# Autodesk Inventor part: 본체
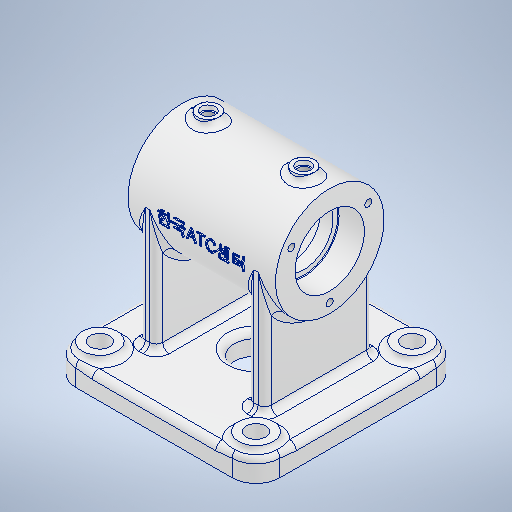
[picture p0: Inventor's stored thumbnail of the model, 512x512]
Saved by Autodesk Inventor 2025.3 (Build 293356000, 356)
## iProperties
Created: 2025-10
Part Number: 본체
Material: 알루미늄 6061
Document SubType Name: Modeling
Designer: USER
Density: 2.7 g/cm^3
Appearance: 알루미늄 - 평지
Mass: 504.67 g
Surface Area: 500.812 cm^2
Volume: 186.915 cm^3
Author: USER
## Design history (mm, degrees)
sketch "스케치1"
  geometry: L1 (-34, 0)-(34, 0); L2 (-34, 0)-(-34, 16); L3 (-34, 16)-(-22.3, 16); L4 (-22, 15.7)-(-22, 13.5); L5 (-22, 13.5)-(-16.258, 13.5); L6 (-16.258, 13.5)-(-5, 20); L7 (-5, 20)-(5, 20); L8 (5, 20)-(16.258, 13.5); L9 (16.258, 13.5)-(22, 13.5); L10 (22, 13.5)-(22, 15.7); L11 (22.3, 16)-(34, 16); L12 (34, 16)-(34, 0); L13 (-34, 25)-(34, 25); L14 (-34, 25)-(-34, 16); L15 (34, 25)-(34, 16); A1 r 0.3 centre (-22.3, 15.7) between (-22, 15.7) and (-22.3, 16); A2 r 0.3 centre (22.3, 15.7) between (22.3, 16) and (22, 15.7); 3 further points
  constraints: 30 end point, 6 perpendicular, 4 point on circle, 4 tangent, 3 vertical, 3 vertical alignment, 2 centre point, 2 coincident, 2 midpoint, 2 point on line, 1 equal radius, 1 horizontal, 1 parallel
  dimensions: "d0" = 12 distance between parallel lines of L4 L2; "d1" = 32 diameter of L3 L1; "d2" = 27 diameter of L5 L1; "d3" = 40 diameter of L7 L1; "d4" = 30 deg angle of L1 L6; "d5" = 30 deg angle of L1 L8; "d6" = 10 distance of L7.end L6.end; "d8" = 32 diameter of L11 L1; "d9" = 12 distance between parallel lines of L10 L12; "d10" = 68 distance between parallel lines of L12 L2; "d11" = 50 diameter of L13 L1; "d12" = 0.3 radius of A1 (derived)
revolve "회전1" sketch "스케치1" stored, may be unused: angle "d13" = 90 deg
node "작업 평면1"
sketch "스케치2"
  geometry: L1 (36, -47)-(-36, -47); L2 (-47, -36)-(-47, 36); L3 (-36, 47)-(36, 47); L4 (47, 36)-(47, -36); L5 (47, -47)-(-47, 47); L6 (-47, -47)-(47, 47); A1 r 11 centre (-36, 36) between (-36, 47) and (-47, 36); A2 r 11 centre (36, 36) between (47, 36) and (36, 47); A3 r 11 centre (36, -36) between (36, -47) and (47, -36); A4 r 11 centre (-36, -36) between (-47, -36) and (-36, -47); 1 further point
  constraints: 12 end point, 8 point on circle, 8 point on line, 8 tangent, 4 centre point, 2 equal radius, 2 midpoint, 2 parallel, 1 horizontal, 1 perpendicular
  dimensions: "d15" = 94 distance between parallel lines of L1 L3; "d16" = 94 distance between parallel lines of L2 L4; "d17" = 11 radius of A1; "d18" = 11 radius of A2
extrude "돌출1" join sketch "스케치2" distance "d19" = 10; taper "d20" = 0 deg
sketch "스케치4"
  geometry: L1 (-36, -47)-(36, -47) reference; L2 (47, -36)-(47, 36) reference; L3 (-36, -47)-(36, -47) reference; L4 (-47, 36)-(-47, -36) reference; L5 (36, 47)-(-36, 47) reference; L6 (47, -36)-(47, 36) reference; C1 r 8 at (36, -36); C2 r 8 at (-36, -36); C3 r 8 at (-36, 36); C4 r 8 at (36, 36); A1 r 11 centre (36, -36) between (36, -47) and (47, -36) reference; A2 r 11 centre (-36, -36) between (-47, -36) and (-36, -47) reference; A3 r 11 centre (-36, 36) between (-36, 47) and (-47, 36) reference; A4 r 11 centre (36, 36) between (47, 36) and (36, 47) reference; A5 r 11 centre (36, -36) between (36, -47) and (47, -36) reference; 1 further point
  constraints: 4 centre point, 4 coincident
  dimensions: "d29" = 16 diameter of C1; "d30" = 16 diameter of C2; "d31" = 16 diameter of C3; "d32" = 16 diameter of C4
extrude "돌출3" join sketch "스케치4" distance "d33" = 3; taper "d34" = 0 deg
sketch "스케치5"
  geometry: C1 r 8 at (-72, 0) reference; C2 r 8 at (0, 0) reference; C3 r 8 at (0, 72) reference; C4 r 8 at (-72, 72) reference; C5 r 4.5 at (-72, 0); C6 r 4.5 at (0, 0); C7 r 4.5 at (0, 72); C8 r 4.5 at (-72, 72); 1 further point
  constraints: 4 centre point, 4 coincident
  dimensions: "d35" = 9 diameter of C5; "d36" = 9 diameter of C6; "d37" = 9 diameter of C7; "d38" = 9 diameter of C8
extrude "돌출4" cut sketch "스케치5" extent not by distance; stored distance "d39" = 0; taper "d40" = 0 deg
node "작업 평면2"
sketch "스케치6"
  geometry: L1 (34, 25)-(34, -25) reference; L2 (-34, 25)-(-34, -25) reference; C1 r 5 at (22, 0); C2 r 5 at (-22, 0); 1 further point
  constraints: 2 centre point, 2 horizontal alignment
  dimensions: "d41" = 12 distance from line of C1.centre L1; "d42" = 12 distance from line of C2.centre L2; "d43" = 10 diameter of C1; "d44" = 10 diameter of C2
extrude "돌출5" join sketch "스케치6" stored distance "d45" = 10; taper "d46" = 0 deg
extrude "돌출6" join sketch "스케치6" distance "d47" = 3; taper "d48" = 0 deg
sketch "스케치7"
  geometry: C1 r 5 at (0, 0) reference; C2 r 5 at (44, 0) reference; C3 r 3.3 at (0, 0); C4 r 3.3 at (44, 0); 1 further point
  constraints: 2 centre point, 2 coincident
  dimensions: "d49" = 6.6 diameter of C3; "d50" = 6.6 diameter of C4
extrude "돌출7" cut sketch "스케치7" distance "d51" = 2; taper "d52" = 0 deg
sketch "스케치8"
  geometry: C1 r 3.3 at (0, 0) reference; C2 r 3.3 at (44, 0) reference; 3 further points
  constraints: 2 coincident
hole "구멍1" sketch "스케치8" at (0, 0), (44, 0) diameter "d53" = 5.1881; stored, may be unused: countersink angle "d57" = 90 deg, drill point angle "d59" = 0 deg; dims "d54" = 12, "d55" = 4, "d56" = 2, "d58" = 16
node "작업 평면3"
sketch "스케치9"
  geometry: C1 r 6 at (0, 0); 1 further point
  constraints: 1 centre point, 1 coincident
  dimensions: "d60" = 12 diameter of C1
extrude "돌출8" join sketch "스케치9" stored distance "d61" = 10; taper "d62" = 0 deg
extrude "돌출9" join sketch "스케치9" distance "d63" = 3; taper "d64" = 0 deg
sketch "스케치10"
  geometry: 1 further point
hole "구멍2" sketch "스케치10" at (0, 0) diameter "d65" = 5.1881; stored, may be unused: countersink angle "d69" = 90 deg, drill point angle "d71" = 0 deg; dims "d66" = 12, "d67" = 4, "d68" = 2, "d70" = 16
sketch "스케치11"
  geometry: C1 r 25 at (0, 0) reference; C2 r 0.5 at (0, -20.5); C3 r 0.5 at (17.754, 10.25); C4 r 0.5 at (-17.754, 10.25); 2 further points
  constraints: 3 centre point, 2 vertical alignment, 1 coincident, 9 other
  dimensions: "d72" = 4.5 dimension on C1; "d73" = 1 diameter of C2; "d76" = 360 deg dimension on point (0, 0) C2.centre (derived)
hole "구멍3" sketch "스케치11" at (-17.754, 10.25), (0, -20.5), (17.754, 10.25) diameter "d78" = 3.242; stored, may be unused: countersink angle "d82" = 90 deg, drill point angle "d84" = 118 deg; dims "d79" = 8, "d80" = 4, "d81" = 2, "d83" = 10
sketch "스케치12"
  geometry: C1 r 10 at (0, 0); 1 further point
  constraints: 1 centre point, 1 coincident
  dimensions: "d85" = 20 diameter of C1
extrude "돌출10" cut sketch "스케치12" extent not by distance; stored distance "d86" = 0; taper "d87" = 0 deg
sketch "스케치13"
  geometry: L1 (26, -25)-(24, -25); L2 (21, -22)-(21, 22); L3 (24, 25)-(26, 25); L4 (29, 22)-(29, -22); L5 (-24, -25)-(-26, -25); L6 (-29, -22)-(-29, 22); L7 (-26, 25)-(-24, 25); L8 (-21, 22)-(-21, -22); A1 r 3 centre (26, -22) between (26, -25) and (29, -22); A2 r 3 centre (24, -22) between (21, -22) and (24, -25); A3 r 3 centre (24, 22) between (24, 25) and (21, 22); A4 r 3 centre (26, 22) between (29, 22) and (26, 25); A5 r 3 centre (-24, -22) between (-24, -25) and (-21, -22); A6 r 3 centre (-26, -22) between (-29, -22) and (-26, -25); A7 r 3 centre (-26, 22) between (-26, 25) and (-29, 22); A8 r 3 centre (-24, 22) between (-21, 22) and (-24, 25); 4 further points
  constraints: 16 end point, 16 point on circle, 16 tangent, 8 centre point, 6 equal radius, 4 parallel, 2 horizontal, 2 horizontal alignment, 2 midpoint, 2 perpendicular
  dimensions: "d96" = 8 distance between parallel lines of L2 L4; "d97" = 50 distance between parallel lines of L3 L1; "d98" = 3 radius of A1 (derived); "d99" = 8 distance between parallel lines of L6 L8; "d100" = 50 distance between parallel lines of L7 L5; "d101" = 3 radius of A5 (derived); "d102" = 21 distance from line of L2 point (0, 0); "d103" = 42 distance between parallel lines of L8 L2
extrude "돌출11" join sketch "스케치13" stored distance "d104" = 10; taper "d105" = 0 deg
fillet "모깎기1" dims "d106" = 3
sketch "스케치14"
  geometry: L1 (-43.455, 8.276)-(43.455, 8.276); L2 (43.455, 8.276)-(43.455, -8.276); L3 (43.455, -8.276)-(-43.455, -8.276); L4 (-43.455, -8.276)-(-43.455, 8.276); 3 further points
  constraints: 2 midpoint, 1 horizontal alignment, 1 vertical alignment, 2 other
feature "엠보싱1" sketch "스케치14" dims "d107" = 0.5, "d108" = 0
node "솔리드1"
mirror "미러1"
node "투영된 루프1"
node "투영된 루프2"
node "투영된 루프3"
node "스케치 - 원형 패턴1" dims "d76" = 360 deg (derived)
feature "A9D066F2-1C7D-4E18-AEED-F7BC21143FA4" dims "d65" = 5.1881, "d66" = 12, "d67" = 4, "d68" = 2, "d69" = 90 deg, "d70" = 16, "d71" = 0
other parameters: "d14" = -66
